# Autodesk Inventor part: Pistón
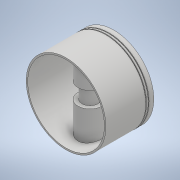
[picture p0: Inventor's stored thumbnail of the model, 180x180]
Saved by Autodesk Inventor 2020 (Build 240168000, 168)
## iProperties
Created: 2019-09
Part Number: Pistón
Material: Generic
Document SubType Name: Modeling
Designer: user
Density: 1 g/cm^3
Appearance: Default
Author: user
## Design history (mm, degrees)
sketch "Sketch1"
  geometry: C1 r 25 at (0, 0); 1 further point
  constraints: 1 centre point, 1 coincident
  dimensions: "d0" = 50 diameter of C1
extrude "Extrusion1" new body sketch "Sketch1" stored distance "d1" = 30; taper "d2" = 0 deg
shell "Shell1" dims "d3" = 1
sketch "Sketch2"
  geometry: C1 r 5 at (0, 0); 1 further point
  constraints: 1 centre point, 1 coincident
  dimensions: "d4" = 10 diameter of C1
extrude "Extrusion2" join sketch "Sketch2" stored distance "d5" = 10; taper "d6" = 0 deg
sketch "Sketch3"
  geometry: C1 r 5 at (0, 0) reference; C2 r 7.5 at (0, 0); 1 further point
  constraints: 1 centre point, 1 coincident
  dimensions: "d7" = 15 diameter of C2
extrude "Extrusion3" join sketch "Sketch3" stored distance "d8" = 10; taper "d9" = 0 deg
sketch "Sketch4"
  geometry: C1 r 5 at (0, 0) reference; C2 r 7.5 at (0, 0); 1 further point
  constraints: 1 centre point, 1 coincident
  dimensions: "d10" = 15 diameter of C2
extrude "Extrusion4" join sketch "Sketch4" stored distance "d11" = 10; taper "d12" = 0 deg
sketch "Sketch5"
  geometry: L1 (20.41, 0)-(8.768, 0); L2 (-15, 25)-(15, 25) reference; L3 (12, 25)-(12, 24.5); L4 (12, 24.5)-(11.5, 24.5); L5 (11.5, 24.5)-(11.5, 25); L6 (12, 25)-(11.75, 25.88); L7 (11.75, 25.88)-(11.5, 25); L8 (10.401, 25)-(10.401, 24.5); L9 (10.401, 24.5)-(9.901, 24.5); L10 (9.901, 24.5)-(9.901, 25); L11 (10.401, 25)-(10.151, 25.88); L12 (10.151, 25.88)-(9.901, 25); 1 further point
  constraints: 22 end point, 4 perpendicular, 2 point on line, 2 vertical, 1 horizontal
  dimensions: "d13" = 0.5 distance of L3.start L3.end; "d14" = 0.5 distance of L3.end L4.end; "d15" = 0.5 distance of L8.start L8.end; "d16" = 0.5 distance of L8.end L9.end
revolve "Revolution1" sketch "Sketch5" stored, may be unused: angle "d17" = 90 deg
body "Solid1"
